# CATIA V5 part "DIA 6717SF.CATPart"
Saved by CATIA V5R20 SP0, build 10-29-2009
Part number: DIA 6717SF
Revision: ANY
Definition: UNKNOWN
Nomenclature: DIA 6717SF
Source: Unknown
Bounding box of the stored display mesh (mm): x -3.35 to 3.35, y -7.95 to 9.02, z -3.186 to 3.186
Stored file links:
  C:\Users\Utente\Desktop\IO LAVORO\3D X SITO CF\CUMSA\3D files FA\FA 126708-21\DIA 6717SF.CATPart
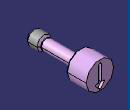
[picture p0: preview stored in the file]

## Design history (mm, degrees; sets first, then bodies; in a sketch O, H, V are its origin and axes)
Body1 "Cortar-Extruir2" (main body)
  Solid1: solid without history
